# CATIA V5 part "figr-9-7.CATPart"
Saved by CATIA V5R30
Part number: Part2
Bounding box of the stored display mesh (mm): x -96.278 to 96.278, y -96.278 to 96.278, z -26.878 to 0
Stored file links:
  D:\PROJECTS\CATIA V56R 2020\Resources\Parts File\c09_catia_v5_6r2020_prt\figr-9-7.CATPart
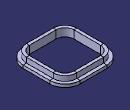
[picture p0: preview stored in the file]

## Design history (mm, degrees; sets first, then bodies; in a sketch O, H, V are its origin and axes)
Body1 (main body)
  Sketch1 on xy-plane, origin (0, 0, 0), H (1, 0, 0), V (0, 1, 0)
    point P1 (-75, 75)
    line L1 (-45, 75) -> (45, 75)
    line L2 (75, 45) -> (75, -45)
    line L3 (45, -75) -> (-45, -75)
    line L4 (-75, -45) -> (-75, 45)
    point P2 (75, 75)
    point P3 (75, -75)
    point P4 (-75, -75)
    axis line L5 (75, -75) -> (-75, 75)
    arc A1 centre (45, -45) radius 30 from (75, -45) to (45, -75) cw
    arc A2 centre (45, 45) radius 30 from (45, 75) to (75, 45) cw
    arc A3 centre (-45, 45) radius 30 from (-45, 75) to (-75, 45) ccw
    arc A4 centre (-45, -45) radius 30 from (-45, -75) to (-75, -45) cw
    distance P2 P3 = 150
    distance P3 P4 = 150
    radius A1 = 30
    radius A2 = 30
    radius A3 = 30
    radius A4 = 30
    horizontal: L1 H, L3 H
    vertical: L2 V, L4 V
    midpoint: O L5
    coincidence: L2 P3, L3 P3, L1 P2, L2 P2, L1 P1, L4 P1, L3 P4, L4 P4
    tangency: A1 L2, A1 L3, A2 L1, A2 L2, A3 L1, A3 L4, A4 L3, A4 L4
  Sketch2 on yz-plane, origin (0, 0, 0), H (0, 1, 0), V (0, 0, 1)
    point P1 (85, 0)
    line L1 (85, 0) -> (85, -16.8782)
    line L2 (85, -16.8782) -> (96.2781, -16.8782)
    line L3 (96.2781, -16.8782) -> (96.2781, -26.8782)
    line L4 (96.2781, -26.8782) -> (75, -26.8782)
    line L5 (75, -26.8782) -> (75, 0)
    point P6 (75, 0)
    line L6 (75, 0) -> (85, 0)
    reference projected point E1 (75, 0) from edge of Sketch1
    length L3 = 10
    length L6 = 10
    coincidence: P1 H, P6 H, P6 E1
    vertical: L1 V, L3 V, L5 V
    horizontal: L2 H, L4 H, L6 H
  Rib1: profile Sketch2, centre curve Sketch1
